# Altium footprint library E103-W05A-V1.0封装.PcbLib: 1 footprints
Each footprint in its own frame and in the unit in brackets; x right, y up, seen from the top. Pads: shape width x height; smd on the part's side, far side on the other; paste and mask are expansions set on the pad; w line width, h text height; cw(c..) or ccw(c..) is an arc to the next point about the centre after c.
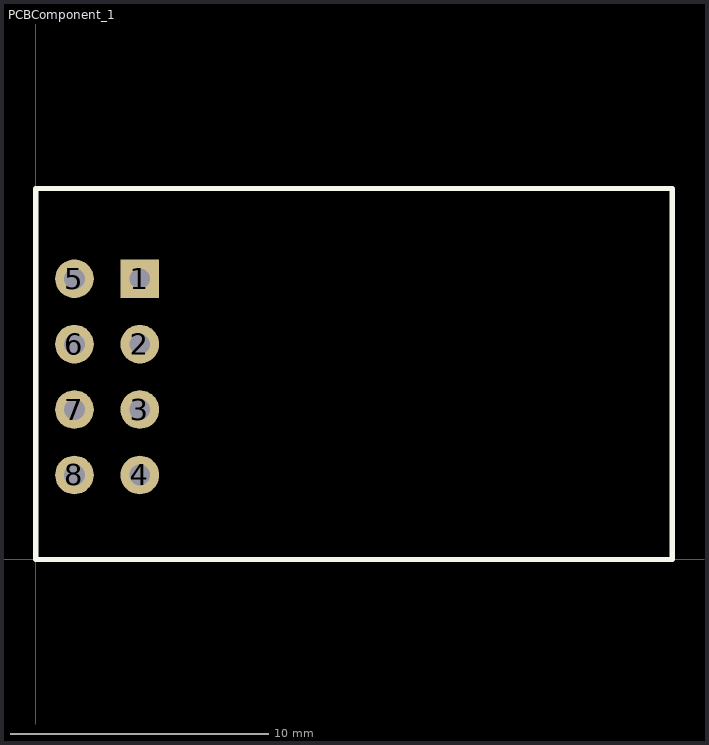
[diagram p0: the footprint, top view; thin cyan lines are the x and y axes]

## PCBComponent_1 [mm]
pads (8):
  rect 1.5x1.5 hole 0.8: 1(4.04,10.9)
  round 1.5 hole 0.8: 2(4.04,8.36) 3(4.04,5.82) 4(4.04,3.28) 5(1.5,10.9) 6(1.5,8.36) 7(1.5,5.82) 8(1.5,3.28)
Top Overlay:
  lines w0.2: 0,0 24.7,0 24.7,14.4 0,14.4 0,0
